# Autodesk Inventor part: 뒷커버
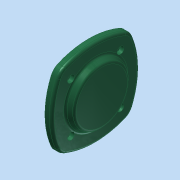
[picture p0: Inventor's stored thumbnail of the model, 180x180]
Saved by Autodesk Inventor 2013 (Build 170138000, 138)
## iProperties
Created: 2015-11
Part Number: 뒷커버
Material: 알루미늄 6061
Document SubType Name: Modeling
Designer: mduedu
Density: 2.71 g/cm^3
Mass: 325.353 g
Surface Area: 247.582 cm^2
Volume: 120.056 cm^3
Author: mduedu
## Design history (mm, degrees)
sketch "스케치1"
  geometry: L1 (50, 50)-(-50, 50); L2 (-50, 50)-(-50, -50); L3 (-50, -50)-(50, -50); L4 (50, -50)-(50, 50); L5 (0, 50)-(0, -50); L6 (50, 0)-(-50, 0); A1 r 90 centre (-40, 0) between (40.415, -40.415) and (40.415, 40.415); A2 r 90 centre (40, 0) between (-40.415, 40.415) and (-40.415, -40.415); A3 r 90 centre (0, -40) between (40.415, 40.415) and (-40.415, 40.415); A4 r 90 centre (0, 40) between (-40.415, -40.415) and (40.415, -40.415); 2 further points
  constraints: 12 end point, 8 point on circle, 5 midpoint, 4 centre point, 2 horizontal alignment, 2 parallel, 2 perpendicular, 2 symmetric about line, 2 tangent, 2 vertical alignment, 1 equal radius, 1 horizontal, 2 other
  dimensions: "d0" = 100 distance of L3.end L1.start; "d2" = 90 radius of A1
extrude "돌출1" new body sketch "스케치1" distance "d3" = 8; taper "d4" = 0 deg
sketch "스케치2"
  geometry: C1 r 35 at (0, 0); 1 further point
  constraints: 1 centre point, 1 coincident
  dimensions: "d5" = 70 diameter of C1
extrude "돌출2" join sketch "스케치2" distance "d6" = 7; taper "d7" = -30 deg
sketch "스케치3"
  geometry: L1 (0, 0)-(0, 40); L2 (0, 0)-(-28.284, 28.284); A1 r 40 centre (0, 0) between (0, 40) and (-28.284, 28.284); 2 further points
  constraints: 4 end point, 2 coincident, 2 point on circle, 1 centre point, 1 vertical
  dimensions: "d8" = 80 diameter of A1; "d9" = 45 deg angle of L1 L2
hole "구멍1" sketch "스케치3" at (-28.284, 28.284) diameter "d11" = 4.5; stored, may be unused: countersink angle "d15" = 90 deg, drill point angle "d17" = 118 deg; dims "d12" = 6, "d13" = 8, "d14" = 4.4, "d16" = 8
sketch "스케치4"
  geometry: C1 r 35 at (0, 0); 1 further point
  constraints: 1 centre point, 1 coincident
  dimensions: "d21" = 70 diameter of C1
extrude "돌출3" join sketch "스케치4" distance "d23" = 12; taper "d24" = 0 deg
hole "구멍2" diameter "d27" = 30; stored, may be unused: countersink angle "d31" = 90 deg, drill point angle "d33" = 0 deg; dims "d25" = 10, "d26" = 10, "d28" = 6, "d29" = 40, "d30" = 12, "d32" = 15
fillet "모깎기2" dims "d35" = 15
fillet "모깎기3" dims "d36" = 3
fillet "모깎기4" dims "d37" = 3
fillet "모깎기5" dims "d38" = 0.3
chamfer "모따기1" distance "d39" = 1; stored, may be unused: second distance "d40" = 2, angle "d41" = 45 deg
node "솔리드1"
pattern_circular "원형 패턴1" dims angle "d19" = 360 deg
